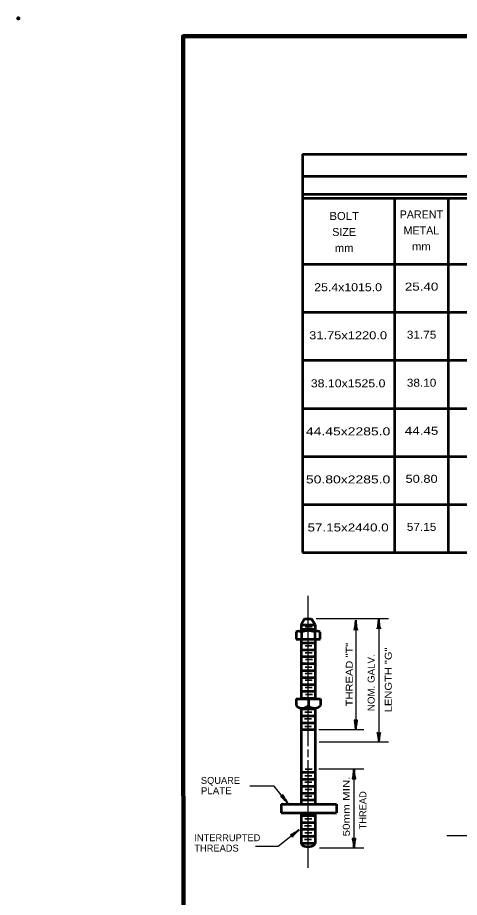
# Model space of a CAD drawing. Extents: x -711 to 145, y 25 to 569.
# Drawn here: x -710.9 to -558, y 264.5 to 569 of the extents above; entities that cross this region are included whole.
import ezdxf
from ezdxf.enums import TextEntityAlignment as Align

# ---------------------------------------------------------------- set-up
doc = ezdxf.new("R2010")
doc.units = 0
doc.header["$LTSCALE"] = 1.1
doc.header["$PDMODE"] = 32
doc.header["$PDSIZE"] = 0.55
doc.layers.add('1', color=7, linetype='Continuous', lineweight=53)

msp = doc.modelspace()

# ---------------------------------------------------------------- linework, layer by layer
at = {"layer": '1'}
for p, q in [((-612.309, 521.791), (-259.32, 521.791)), ((-612.309, 521.791), (-612.309, 383.884)), ((-612.309, 514.168), (-259.32, 514.168)), ((-612.309, 507.931), (-259.32, 507.931)), ((-612.309, 506.545), (-259.32, 506.545)), ((-580.398, 506.276), (-580.398, 383.615)), ((-561.873, 506.545), (-561.873, 383.884)), ((-612.309, 483.676), (-366.042, 483.676)), ((-612.309, 467.044), (-366.042, 467.044)), ((-612.309, 450.412), (-366.042, 450.412)), ((-612.309, 433.78), (-366.042, 433.78)), ((-612.309, 417.148), (-366.042, 417.148)), ((-612.309, 400.516), (-366.042, 400.516)), ((-612.309, 383.884), (-366.042, 383.884)), ((-611.59, 360.943), (-612.729, 358.867)), ((-611.59, 360.943), (-609.19, 360.943)), ((-609.19, 360.943), (-607.929, 358.867)), ((-612.729, 358.867), (-607.929, 358.867)), ((-612.729, 358.867), (-612.729, 356.362)), ((-612.729, 357.34), (-607.929, 357.34)), ((-607.929, 358.867), (-607.929, 356.38)), ((-614.488, 356.315), (-614.488, 353.874)), ((-614.488, 353.874), (-606.139, 353.874)), ((-612.729, 353.864), (-612.729, 333.229)), ((-612.729, 353.849), (-607.929, 353.849)), ((-612.637, 356.284), (-612.637, 353.865)), ((-608.041, 356.286), (-608.041, 353.844)), ((-607.929, 353.864), (-607.929, 333.331)), ((-606.139, 353.864), (-606.139, 356.266)), ((-612.729, 352.649), (-607.929, 352.649)), ((-612.729, 350.249), (-607.929, 350.249)), ((-612.729, 347.849), (-607.929, 347.849)), ((-612.729, 345.449), (-607.929, 345.449)), ((-612.729, 343.049), (-607.929, 343.049)), ((-612.729, 340.649), (-607.929, 340.649)), ((-612.729, 338.249), (-607.929, 338.249)), ((-612.729, 335.849), (-607.929, 335.849)), ((-612.647, 333.449), (-607.929, 333.449)), ((-610.228, 333.193), (-610.228, 330.851)), ((-606.025, 333.214), (-606.025, 330.913)), ((-612.741, 329.776), (-607.941, 329.776)), ((-612.729, 330.057), (-612.729, 324.277)), ((-607.929, 330.006), (-607.929, 324.226)), ((-612.741, 327.376), (-607.941, 327.376)), ((-612.741, 324.976), (-607.941, 324.976)), ((-612.729, 325.153), (-612.729, 296.723)), ((-607.929, 325.172), (-607.929, 296.712)), ((-612.741, 322.576), (-607.941, 322.576)), ((-612.729, 307.823), (-607.929, 307.823)), ((-612.729, 305.423), (-607.929, 305.423)), ((-612.729, 303.023), (-607.929, 303.023)), ((-612.729, 300.623), (-607.929, 300.623)), ((-619.652, 296.764), (-600.452, 296.764)), ((-619.652, 296.764), (-619.652, 293.764)), ((-612.729, 298.223), (-607.929, 298.223)), ((-600.493, 296.723), (-600.493, 293.723)), ((-619.652, 293.764), (-600.452, 293.764)), ((-612.729, 293.723), (-612.729, 283.267)), ((-612.729, 292.867), (-607.929, 292.867)), ((-607.929, 293.726), (-607.929, 283.267)), ((-612.729, 290.467), (-607.929, 290.467)), ((-612.729, 288.067), (-607.929, 288.067)), ((-612.729, 285.667), (-607.929, 285.667)), ((-612.729, 283.267), (-607.929, 283.267))]:
    msp.add_line(p, q, dxfattribs=at)
at = {"layer": '1', "lineweight": 25}
for p, q in [((-610.268, 316.88), (-610.268, 368.918)), ((-607.532, 361.005), (-582.509, 361.005)), ((-593.824, 360.495), (-593.824, 322.434)), ((-585.844, 360.904), (-585.844, 318.137)), ((-606.611, 322.591), (-591.011, 322.591)), ((-606.509, 318.295), (-582.509, 318.295)), ((-610.268, 313.034), (-610.268, 315.653)), ((-610.268, 274.685), (-610.268, 312.053)), ((-606.611, 308.985), (-591.011, 308.985)), ((-594.437, 308.935), (-594.437, 281.517)), ((-562.314, 285.884), (-525.207, 285.884)), ((-606.407, 281.62), (-591.011, 281.62))]:
    msp.add_line(p, q, dxfattribs=at)
at = {"layer": '1', "lineweight": 35}
for p, q in [((-611.307, 358.152), (-608.907, 358.152)), ((-611.389, 351.607), (-608.989, 351.607)), ((-611.307, 349.153), (-608.907, 349.153)), ((-611.389, 344.244), (-608.989, 344.244)), ((-611.225, 346.862), (-608.825, 346.862)), ((-611.307, 341.953), (-608.907, 341.953)), ((-611.307, 339.662), (-608.907, 339.662)), ((-611.307, 337.208), (-608.907, 337.208)), ((-611.225, 334.753), (-608.825, 334.753)), ((-611.542, 326.267), (-609.142, 326.267)), ((-611.44, 328.62), (-609.04, 328.62)), ((-611.491, 323.71), (-609.091, 323.71)), ((-611.368, 308.931), (-608.968, 308.931)), ((-611.42, 306.629), (-609.02, 306.629)), ((-611.471, 304.4), (-609.071, 304.4)), ((-611.389, 301.864), (-608.989, 301.864)), ((-611.471, 299.573), (-609.071, 299.573)), ((-611.471, 291.719), (-609.071, 291.719)), ((-611.512, 289.305), (-609.112, 289.305)), ((-611.471, 286.892), (-609.071, 286.892)), ((-611.553, 284.56), (-609.153, 284.56))]:
    msp.add_line(p, q, dxfattribs=at)
at = {"layer": '1', "lineweight": 158}
msp.add_lwpolyline([(138.105, 562.675), (-653.595, 562.575), (-653.495, 36.575)], dxfattribs=at)
at = {"layer": '1'}
for points in [[(-614.452, 333.214), (-612.812, 333.214), (-606.025, 333.214)], [(-614.452, 333.214), (-614.452, 330.887), (-614.452, 330.872)]]:
    msp.add_lwpolyline(points, dxfattribs=at)
at = {"layer": '1', "lineweight": 25}
for points in [[(-617.353, 297.067), (-622.059, 303.001), (-630.487, 303.001)], [(-613.465, 287.86), (-620.627, 282.131), (-628.532, 282.131)]]:
    msp.add_lwpolyline(points, dxfattribs=at)
at = {"layer": '1'}
for centre, radius, start, end in [((-613.577, 355.274), 1.38, 47.02481, 134.15589), ((-610.337, 351.824), 5.018, 62.77444, 117.28042), ((-607.1, 355.276), 1.38, 45.84411, 132.97519), ((-612.33, 332.968), 2.983, 223.91036, 261.22257), ((-612.33, 332.968), 2.983, 260.70482, 314.79453), ((-612.33, 332.968), 2.983, 260.88259, 261.22257), ((-612.33, 332.968), 2.983, 261.22257, 315.06188), ((-608.137, 333.009), 2.983, 225.20547, 315.348)]:
    msp.add_arc(centre, radius, start, end, dxfattribs=at)
at = {"layer": '1', "lineweight": 40}
for centre, major_axis, ratio, start_param, end_param in [((-594.077, 359.15), (-0.211, -2.108), 0.07063, 6.2823074, 8.5597026), ((-593.492, 359.185), (-0.187, 2.143), 0.122415, 0.8963533, 3.1415927), ((-586.098, 359.559), (-0.211, -2.108), 0.07063, 6.2823074, 8.5597026), ((-585.512, 359.595), (-0.187, 2.143), 0.122415, 0.8963533, 3.1415927), ((-594.155, 323.743), (0.187, -2.143), 0.122415, 0.8963533, 3.1415927), ((-593.57, 323.778), (0.211, 2.108), 0.07063, 6.2823074, 8.5597026), ((-586.175, 319.447), (0.187, -2.143), 0.122415, 0.8963533, 3.1415927), ((-585.59, 319.482), (0.211, 2.108), 0.07063, 6.2823074, 8.5597026), ((-594.691, 307.59), (-0.211, -2.108), 0.07063, 6.2823074, 8.5597026), ((-594.106, 307.625), (-0.187, 2.143), 0.122415, 0.8963533, 3.1415927), ((-618.426, 297.887), (1.478, -1.562), 0.122415, 0.8963533, 3.1415927), ((-617.989, 298.279), (-1.145, 1.782), 0.07063, 6.2823074, 8.5597026), ((-614.674, 287.219), (-1.778, -1.152), 0.07063, 6.2823074, 8.5597026), ((-614.281, 286.783), (1.556, 1.485), 0.122415, 0.8963533, 3.1415927), ((-594.769, 282.826), (0.187, -2.143), 0.122415, 0.8963533, 3.1415927), ((-594.183, 282.861), (0.211, 2.108), 0.07063, 6.2823074, 8.5597026)]:
    msp.add_ellipse(centre, major_axis=major_axis, ratio=ratio, start_param=start_param, end_param=end_param, dxfattribs=at)
at = {"layer": '1'}
msp.add_ellipse((-610.329, 283.267), major_axis=(-2.4, 0), ratio=0.511868, start_param=6.2831853, end_param=9.424778, dxfattribs=at)
msp.add_point((-710.595, 568.775), dxfattribs=at)

# ---------------------------------------------------------------- texts
for s, width, p in [('BOLT', 1.05, (-597.846, 498.998)), ('mm', 1.05, (-571.114, 488.448)), ('mm', 1.05, (-597.846, 487.91)), ('25.4x1015.0', 1.15, (-596.471, 474.331)), ('25.40', 1.25, (-571.042, 474.536)), ('31.75x1220.0', 1.2, (-596.471, 457.699)), ('31.75', 1.1, (-571.042, 457.904)), ('38.10x1525.0', 1.15, (-596.471, 441.067)), ('38.10', 1.1, (-571.042, 441.272)), ('44.45x2285.0', 1.3, (-596.471, 424.435)), ('44.45', 1.25, (-571.042, 424.64)), ('50.80x2285.0', 1.3, (-596.471, 407.803)), ('50.80', 1.2, (-571.042, 408.008)), ('57.15x2440.0', 1.25, (-596.471, 391.171)), ('57.15', 1.1, (-571.042, 391.376))]:
    msp.add_text(s, height=2.772, dxfattribs=dict(at, width=width)).set_placement(p, align=Align.CENTER)
for s, p in [('PARENT', (-571.114, 499.536)), ('METAL', (-571.114, 493.992)), ('SIZE', (-597.846, 493.454))]:
    msp.add_text(s, height=2.772, dxfattribs=at).set_placement(p, align=Align.CENTER)
for s, width, p in [('THREAD "T"', 1.2, (-594.874, 330.623)), ('LENGTH "G"', 1.2, (-581.37, 328.577)), ('NOM. GALV.', 1.05, (-587.304, 328.986)), ('50mm MIN.', 1.25, (-595.897, 285.632))]:
    msp.add_text(s, height=2.4, rotation=90, dxfattribs=dict(at, width=width)).set_placement(p)
for s, p in [('SQUARE', (-647.43, 303.806)), ('INTERRUPTED', (-649.68, 283.959)), ('THREADS', (-649.68, 280.359))]:
    msp.add_text(s, height=2.4, dxfattribs=at).set_placement(p)
at = {"layer": '1', "width": 1.05}
msp.add_text('PLATE', height=2.4, dxfattribs=at).set_placement((-647.43, 300.206))
at = {"layer": '1'}
msp.add_text('THREAD', height=2.4, rotation=90, dxfattribs=at).set_placement((-590.168, 288.065))

doc.saveas('drawing.dxf')
